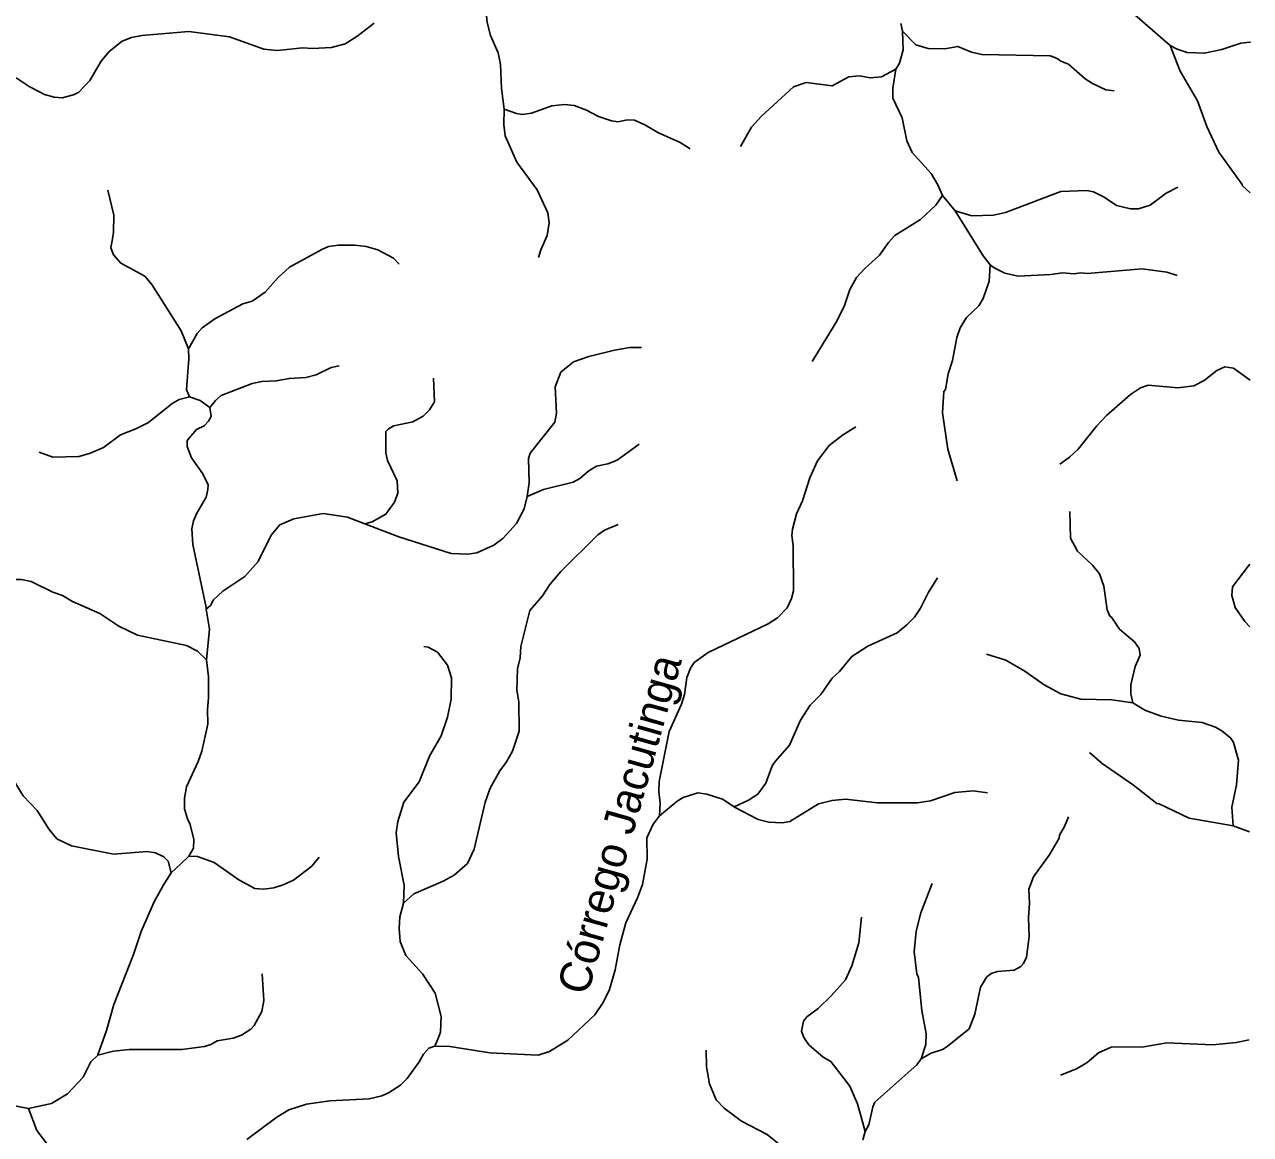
# Model space of a CAD drawing. Extents: x 500 to 555.2, y 9115.7 to 9171.
# Drawn here: x 549 to 555.13, y 9138.81 to 9144.36 of the extents above; entities that cross this region are included whole.
import ezdxf
from ezdxf.enums import TextEntityAlignment as Align

# ---------------------------------------------------------------- set-up
doc = ezdxf.new("R2010")
doc.units = 0
doc.header["$LTSCALE"] = 0.064
doc.layers.add('61', color=7, linetype='Continuous')
doc.layers.add('7', color=7, linetype='Continuous', lineweight=25)

msp = doc.modelspace()

# ---------------------------------------------------------------- linework, layer by layer
at = {"layer": '7'}
for p, q in [((553.6562, 9143.4292), (553.5928, 9143.5056)), ((555.0479, 9140.3515), (555.1299, 9140.3215))]:
    msp.add_line(p, q, dxfattribs=at)
for points in [[(551.3988, 9143.9379), (551.3851, 9144.0421), (551.3815, 9144.1623), (551.3685, 9144.2203), (551.3311, 9144.3079), (551.3147, 9144.3725), (551.3048, 9144.4766), (551.3209, 9144.649), (551.3179, 9144.7388), (551.3368, 9144.836)], [(554.7331, 9144.2576), (554.7328, 9144.2578), (554.5308, 9144.4333)], [(548.9572, 9144.0957), (549.0224, 9144.0519), (549.0979, 9144.0118), (549.1466, 9143.9984), (549.1866, 9143.9952), (549.2444, 9144.0096), (549.2707, 9144.0231), (549.3248, 9144.0821), (549.3823, 9144.1788), (549.422, 9144.2269), (549.4867, 9144.2785), (549.5345, 9144.2972), (549.5856, 9144.3067), (549.8212, 9144.328), (550.0246, 9144.3003), (550.1965, 9144.2395), (550.2634, 9144.233), (550.392, 9144.2459), (550.44, 9144.2428), (550.5343, 9144.2479), (550.6026, 9144.2658), (550.6621, 9144.3027), (550.7492, 9144.3699)], [(553.3588, 9144.1394), (553.3782, 9144.1697), (553.3959, 9144.2363), (553.3924, 9144.3284)], [(553.3924, 9144.3284), (553.3838, 9144.3669)], [(554.4516, 9144.0301), (554.4101, 9144.0349), (554.3431, 9144.0669), (554.3076, 9144.0907), (554.2232, 9144.1636), (554.1853, 9144.1783), (554.1719, 9144.1884), (554.1562, 9144.1969), (554.1317, 9144.2049), (553.79, 9144.213), (553.7388, 9144.2232), (553.6693, 9144.2524), (553.6043, 9144.2412), (553.5208, 9144.2431), (553.4602, 9144.261), (553.3924, 9144.3284)], [(555.1346, 9144.2746), (555.1308, 9144.2741), (555.0857, 9144.2682), (554.9914, 9144.2377), (554.9028, 9144.2182), (554.8175, 9144.2228), (554.7683, 9144.2388), (554.7331, 9144.2576)], [(555.1337, 9143.5192), (555.094, 9143.5541), (555.0932, 9143.5622), (554.9765, 9143.7226), (554.9168, 9143.8518), (554.869, 9143.9803), (554.7831, 9144.1294), (554.7331, 9144.2576)], [(552.5821, 9143.7511), (552.6366, 9143.8491), (552.6862, 9143.902), (552.8466, 9144.0507), (552.9115, 9144.0722), (553.0401, 9144.0559), (553.124, 9144.1006), (553.1781, 9144.105), (553.2303, 9144.0952), (553.288, 9144.1006), (553.3588, 9144.1394)], [(553.5928, 9143.5056), (553.5698, 9143.5605), (553.537, 9143.6162), (553.4406, 9143.7224), (553.4139, 9143.7809), (553.3912, 9143.8944), (553.3452, 9143.9932), (553.3452, 9144.0434), (553.3588, 9144.1394)], [(552.33, 9143.7402), (552.2793, 9143.7718), (552.1679, 9143.821), (552.1034, 9143.8606), (552.0513, 9143.8828), (552.0171, 9143.8852), (551.9679, 9143.8755), (551.9365, 9143.8799), (551.871, 9143.9012), (551.8115, 9143.9328), (551.7496, 9143.9576), (551.7011, 9143.9623), (551.6381, 9143.9555), (551.5353, 9143.9179), (551.4904, 9143.9116), (551.4605, 9143.9164), (551.3988, 9143.9379)], [(551.571, 9143.1957), (551.5826, 9143.2347), (551.615, 9143.3065), (551.6244, 9143.3689), (551.6179, 9143.4194), (551.565, 9143.5347), (551.4631, 9143.6732), (551.4047, 9143.8056), (551.3982, 9143.8615), (551.3988, 9143.9379)], [(549.4154, 9143.5324), (549.4461, 9143.4074), (549.4443, 9143.3233), (549.4387, 9143.2894), (549.43, 9143.2442), (549.4446, 9143.2092), (549.4807, 9143.1679), (549.6005, 9143.1022), (549.6356, 9143.0612), (549.782, 9142.8295), (549.8196, 9142.7384)], [(554.7707, 9143.5473), (554.7133, 9143.5177), (554.6327, 9143.4572), (554.5748, 9143.4391), (554.5347, 9143.4392), (554.4633, 9143.4557), (554.4021, 9143.4975), (554.3484, 9143.5244), (554.3157, 9143.5309), (554.1854, 9143.526), (553.9089, 9143.4209), (553.8491, 9143.4083), (553.7396, 9143.4038), (553.6562, 9143.4292)], [(552.9406, 9142.6752), (553.0646, 9142.8765), (553.1024, 9142.9552), (553.1289, 9143.036), (553.1619, 9143.0962), (553.2037, 9143.1417), (553.2776, 9143.2075), (553.3223, 9143.2717), (553.3546, 9143.3056), (553.4834, 9143.387), (553.56, 9143.4572), (553.5928, 9143.5056)], [(553.8322, 9143.159), (553.7967, 9143.2042), (553.6562, 9143.4292)], [(550.8738, 9143.1621), (550.8452, 9143.1928), (550.7672, 9143.2338), (550.7082, 9143.2519), (550.6518, 9143.2586), (550.5693, 9143.2586), (550.5207, 9143.2504), (550.4866, 9143.2369), (550.3241, 9143.1471), (550.2676, 9143.0959), (550.2031, 9143.0232), (550.1375, 9142.977), (550.0914, 9142.9634), (549.9512, 9142.8887), (549.8871, 9142.8446), (549.8625, 9142.815), (549.8196, 9142.7384)], [(553.6667, 9142.0777), (553.6195, 9142.2371), (553.5929, 9142.4183), (553.6004, 9142.5245), (553.6076, 9142.5359), (553.6218, 9142.6135), (553.6437, 9142.6812), (553.6651, 9142.796), (553.6808, 9142.8434), (553.7129, 9142.8949), (553.7745, 9142.9533), (553.7969, 9142.9911), (553.827, 9143.077), (553.8322, 9143.159)], [(554.7683, 9143.1063), (554.7159, 9143.1225), (554.5932, 9143.1389), (554.3179, 9143.1167), (554.2835, 9143.1191), (554.2524, 9143.1143), (554.1942, 9143.1192), (554.1351, 9143.111), (553.9717, 9143.1029), (553.9054, 9143.1175), (553.8513, 9143.144), (553.8322, 9143.159)], [(549.8196, 9142.7384), (549.8212, 9142.6888), (549.8096, 9142.5345), (549.8237, 9142.4982)], [(552.0874, 9142.7447), (552.0275, 9142.7449), (551.951, 9142.7321), (551.8231, 9142.7009), (551.746, 9142.6743), (551.6824, 9142.6224), (551.6538, 9142.5479), (551.6607, 9142.4164), (551.6522, 9142.3717), (551.5296, 9142.2171), (551.5215, 9142.1895), (551.5244, 9142.0672), (551.5139, 9141.9995)], [(550.5742, 9142.653), (550.5337, 9142.6449), (550.4579, 9142.6085), (550.4058, 9142.596), (550.3243, 9142.591), (550.2581, 9142.578), (550.1866, 9142.5746), (550.1385, 9142.5645), (549.9822, 9142.5047), (549.9537, 9142.4802), (549.9256, 9142.4453)], [(551.0451, 9142.5921), (551.0509, 9142.4735), (551.0259, 9142.4335), (550.9935, 9142.4012), (550.9426, 9142.3727), (550.8474, 9142.3527), (550.82, 9142.3385), (550.8077, 9142.3245), (550.8063, 9142.2188), (550.8153, 9142.1797), (550.8633, 9142.0776), (550.8662, 9142.0164), (550.8507, 9141.9714), (550.8067, 9141.9111), (550.7391, 9141.873), (550.7011, 9141.863)], [(555.1326, 9142.5815), (555.1207, 9142.5902), (555.0488, 9142.6428), (555.0063, 9142.6484), (554.9654, 9142.63), (554.9024, 9142.5799), (554.8516, 9142.5537), (554.7708, 9142.5435), (554.6226, 9142.5565), (554.5839, 9142.5428), (554.5334, 9142.5095), (554.4135, 9142.4045), (554.365, 9142.3526), (554.2724, 9142.2372), (554.2282, 9142.1963), (554.1801, 9142.1613)], [(549.0726, 9142.2221), (549.1396, 9142.1959), (549.2698, 9142.1995), (549.3238, 9142.214), (549.3932, 9142.2456), (549.4791, 9142.3089), (549.5565, 9142.338), (549.6199, 9142.3696), (549.7377, 9142.4644), (549.7726, 9142.4859), (549.8237, 9142.4982)], [(549.8237, 9142.4982), (549.8775, 9142.4808), (549.9256, 9142.4453)], [(549.9256, 9142.4453), (549.9331, 9142.4005), (549.92, 9142.3762), (549.8976, 9142.3535), (549.8594, 9142.3353), (549.812, 9142.2795), (549.8126, 9142.2493), (549.8343, 9142.1939), (549.891, 9142.1131), (549.9169, 9142.0582), (549.9168, 9142.035), (549.907, 9141.9957), (549.8605, 9141.9154), (549.8448, 9141.8775), (549.8367, 9141.8374), (549.8417, 9141.7588), (549.907, 9141.4434), (549.9081, 9141.4362)], [(553.1591, 9142.3481), (553.0927, 9142.3072), (553.0261, 9142.2555), (552.9673, 9142.1779), (552.9284, 9142.0935), (552.892, 9141.978), (552.8631, 9141.9136), (552.8417, 9141.836), (552.8384, 9141.8047), (552.8465, 9141.7528), (552.8481, 9141.5271), (552.8379, 9141.4892), (552.8165, 9141.4424), (552.7681, 9141.3923), (552.7206, 9141.3627), (552.4209, 9141.2186), (552.3508, 9141.1683), (552.3325, 9141.1399), (552.3142, 9141.0932), (552.3018, 9141.0081), (552.2876, 9140.9601), (552.2251, 9140.8233), (552.1754, 9140.573), (552.1741, 9140.5226), (552.1804, 9140.4649), (552.1765, 9140.4001)], [(552.0747, 9142.2615), (551.9656, 9142.181), (551.9177, 9142.1628), (551.8618, 9142.151), (551.8236, 9142.1287), (551.7786, 9142.0892), (551.7448, 9142.0714), (551.5967, 9142.0348), (551.5139, 9141.9995)], [(551.5139, 9141.9995), (551.5001, 9141.9386), (551.4617, 9141.864), (551.3927, 9141.7901), (551.3467, 9141.7558), (551.2627, 9141.7173), (551.2168, 9141.7103), (551.1334, 9141.7141), (550.8727, 9141.7979), (550.7011, 9141.863)], [(554.2303, 9141.9246), (554.2344, 9141.7905), (554.268, 9141.7256), (554.3446, 9141.6556), (554.3781, 9141.6124), (554.4002, 9141.5515), (554.4177, 9141.4327), (554.4307, 9141.4011), (554.4392, 9141.3962), (554.4791, 9141.3358), (554.5534, 9141.2713), (554.577, 9141.2393), (554.5817, 9141.2051), (554.5572, 9141.1486), (554.5361, 9141.0567), (554.5361, 9141.0114), (554.5458, 9140.9663)], [(550.7011, 9141.863), (550.6157, 9141.8954), (550.4937, 9141.9151), (550.3461, 9141.8871), (550.2763, 9141.8577), (550.2336, 9141.8053), (550.1679, 9141.6742), (550.1012, 9141.5997), (549.9919, 9141.526), (549.9451, 9141.4818), (549.9301, 9141.454), (549.9081, 9141.4362)], [(551.9705, 9141.8597), (551.9018, 9141.8315), (551.868, 9141.8078), (551.6834, 9141.6249), (551.6282, 9141.5596), (551.5912, 9141.5024), (551.5271, 9141.4282), (551.4821, 9141.2489), (551.4785, 9141.1925), (551.4655, 9141.1365), (551.4622, 9141.0298), (551.4719, 9140.9714), (551.4751, 9140.8245), (551.4402, 9140.7249), (551.4113, 9140.6719), (551.3769, 9140.6266), (551.3287, 9140.5386), (551.3043, 9140.4688), (551.2488, 9140.2345), (551.2154, 9140.1619), (551.1487, 9140.1036), (551.0947, 9140.0732), (550.9469, 9140.01), (550.8951, 9139.9642)], [(555.1312, 9141.3476), (555.1304, 9141.3484), (555.1067, 9141.3737), (555.0582, 9141.4438), (555.0413, 9141.5042), (555.045, 9141.5466), (555.1249, 9141.6528), (555.1316, 9141.6616)], [(548.7933, 9141.3636), (548.8368, 9141.423), (548.8724, 9141.5271), (548.9023, 9141.5694), (548.9324, 9141.5836), (548.9842, 9141.5836), (549.0312, 9141.5738), (549.1401, 9141.5213), (549.1892, 9141.5032), (549.238, 9141.474), (549.3757, 9141.4132), (549.4713, 9141.35), (549.5639, 9141.3059), (549.8091, 9141.2538), (549.864, 9141.225), (549.9093, 9141.1821)], [(553.5682, 9141.5923), (553.5213, 9141.5177), (553.4832, 9141.4401), (553.4526, 9141.3961), (553.4151, 9141.3569), (553.3666, 9141.3174), (553.2189, 9141.2509), (553.1385, 9141.1984), (553.077, 9141.124), (553.0413, 9141.0894), (552.9837, 9141.0078), (552.9307, 9140.9545), (552.8827, 9140.8802), (552.8268, 9140.7547), (552.7548, 9140.6735), (552.741, 9140.6505), (552.7083, 9140.5643), (552.6681, 9140.5101), (552.6215, 9140.4799), (552.5496, 9140.446)], [(549.9081, 9141.4362), (549.9236, 9141.3351), (549.9093, 9141.1821)], [(550.9966, 9141.2494), (551.0188, 9141.2449), (551.0652, 9141.2195), (551.1148, 9141.1549), (551.1356, 9141.0913), (551.134, 9140.9852), (551.1148, 9140.8951), (551.0847, 9140.8016), (551.025, 9140.6996), (550.9738, 9140.5715), (550.8976, 9140.4698), (550.8667, 9140.3728), (550.8585, 9140.3151), (550.8707, 9140.1969), (550.8994, 9140.0542), (550.8951, 9139.9642)], [(549.9093, 9141.1821), (549.9201, 9141.0974), (549.9202, 9140.9911), (549.9136, 9140.9333), (549.9168, 9140.8606), (549.8856, 9140.7254), (549.8671, 9140.6722), (549.8085, 9140.5462), (549.7988, 9140.4892), (549.7991, 9140.4367), (549.8135, 9140.3855), (549.8284, 9140.358), (549.846, 9140.2823), (549.8446, 9140.2388), (549.8211, 9140.1991)], [(553.8139, 9141.2108), (553.91, 9141.18), (554.0051, 9141.1259), (554.1025, 9141.0561), (554.1859, 9141.0112), (554.2854, 9140.9853), (554.4401, 9140.9819), (554.5458, 9140.9663)], [(554.5458, 9140.9663), (554.6063, 9140.9307), (554.6869, 9140.8999), (554.7741, 9140.8804), (554.8936, 9140.8687), (554.9592, 9140.8441), (554.992, 9140.826), (555.036, 9140.79), (555.0492, 9140.7686), (555.074, 9140.6801), (555.0642, 9140.5561), (555.0406, 9140.4438), (555.0479, 9140.3515)], [(548.9218, 9140.8426), (548.9181, 9140.7609), (548.9266, 9140.6297), (548.9425, 9140.5823), (548.9922, 9140.5014), (549.0611, 9140.427), (549.1211, 9140.3318), (549.161, 9140.285), (549.2336, 9140.2502), (549.4433, 9140.2095), (549.612, 9140.2223), (549.6545, 9140.2159), (549.6966, 9140.1965), (549.718, 9140.1735), (549.7331, 9140.1163)], [(554.3287, 9140.7178), (554.3918, 9140.6621), (554.5496, 9140.5551), (554.666, 9140.4628), (554.678, 9140.4615), (554.8276, 9140.39), (555.0479, 9140.3515)], [(552.5496, 9140.446), (552.492, 9140.4848), (552.4135, 9140.5094), (552.3681, 9140.516), (552.2955, 9140.493), (552.2659, 9140.475), (552.1765, 9140.4001)], [(553.8182, 9140.5167), (553.7463, 9140.5259), (553.6541, 9140.5178), (553.5328, 9140.4752), (553.4673, 9140.4653), (553.2685, 9140.4653), (553.1069, 9140.4848), (553.0402, 9140.4783), (552.9719, 9140.4604), (552.8283, 9140.3725), (552.7907, 9140.3652), (552.7234, 9140.3694), (552.6699, 9140.3832), (552.5513, 9140.4449), (552.5496, 9140.446)], [(552.1765, 9140.4001), (552.1443, 9140.3596), (552.1132, 9140.2916), (552.1148, 9140.1848), (552.0921, 9140.0575), (552.0671, 9139.9906), (552.0082, 9139.8659), (551.9785, 9139.7549), (551.9556, 9139.6297), (551.926, 9139.5313), (551.8948, 9139.4658), (551.8535, 9139.4052), (551.718, 9139.2777), (551.6255, 9139.2216), (551.5697, 9139.2029), (551.3276, 9139.2137), (551.1281, 9139.2466), (551.053, 9139.2481)], [(554.2232, 9140.3961), (554.2039, 9140.3472), (554.1787, 9140.3043), (554.1766, 9140.2899), (554.131, 9140.2083), (554.0486, 9140.0948), (554.026, 9140.0332), (554.029, 9139.9629), (554.0242, 9139.8913), (554.0275, 9139.797), (554.0131, 9139.6939), (553.9992, 9139.661), (553.986, 9139.6465), (553.9523, 9139.6283), (553.868, 9139.6216), (553.8372, 9139.6122), (553.8151, 9139.5948), (553.7833, 9139.5433), (553.7554, 9139.4078), (553.7258, 9139.3351), (553.6168, 9139.2455), (553.5928, 9139.2318), (553.5359, 9139.2122), (553.4861, 9139.1849)], [(549.8211, 9140.1991), (549.7804, 9140.1614), (549.7331, 9140.1163)], [(550.4732, 9140.1944), (550.4365, 9140.1482), (550.3453, 9140.0792), (550.2937, 9140.055), (550.247, 9140.0409), (550.194, 9140.0338), (550.1506, 9140.0371), (550.0706, 9140.0801), (549.9477, 9140.1675), (549.8651, 9140.1976), (549.8211, 9140.1991)], [(549.7331, 9140.1163), (549.6931, 9140.0525), (549.6461, 9139.9676), (549.5826, 9139.8212), (549.5448, 9139.7063), (549.4459, 9139.457), (549.4085, 9139.3258), (549.3659, 9139.2049), (549.3649, 9139.2035)], [(553.5408, 9140.0616), (553.4846, 9139.9152), (553.4616, 9139.8233), (553.4519, 9139.7195), (553.465, 9139.6093), (553.4727, 9139.5912), (553.4897, 9139.4264), (553.5108, 9139.3102), (553.509, 9139.2563), (553.4861, 9139.1849)], [(550.8951, 9139.9642), (550.8765, 9139.8953), (550.8733, 9139.8364), (550.8791, 9139.7719), (550.9065, 9139.7021), (550.9913, 9139.6106), (551.0533, 9139.5128), (551.0843, 9139.3967), (551.0813, 9139.3186), (551.0665, 9139.2826), (551.053, 9139.2481)], [(553.1871, 9139.8929), (553.1745, 9139.7648), (553.14, 9139.6501), (553.1068, 9139.5792), (553.0367, 9139.4991), (552.97, 9139.4371), (552.9138, 9139.3941), (552.8971, 9139.3732), (552.8875, 9139.3229), (552.8999, 9139.2908), (552.9249, 9139.255), (552.9959, 9139.1936), (553.0339, 9139.1704), (553.1295, 9139.0476), (553.1675, 9138.9592), (553.206, 9138.821)], [(550.1885, 9139.6103), (550.1959, 9139.477), (550.1859, 9139.4217), (550.1484, 9139.3511), (550.1309, 9139.3327), (550.0838, 9139.3037), (550.0429, 9139.2887), (549.9635, 9139.2744), (549.9306, 9139.2559), (549.8994, 9139.2463), (549.7851, 9139.2318), (549.5219, 9139.2316), (549.4446, 9139.2235), (549.3649, 9139.2035)], [(554.1836, 9139.1031), (554.2642, 9139.1337), (554.318, 9139.1658), (554.3732, 9139.2142), (554.4371, 9139.243), (554.601, 9139.2449), (554.7165, 9139.2645), (554.9454, 9139.2547), (555.0635, 9139.2661), (555.1282, 9139.2794), (555.1287, 9139.2795)], [(551.053, 9139.2481), (551.0228, 9139.2374), (550.9947, 9139.2071), (550.9741, 9139.1697), (550.9136, 9139.0852), (550.8798, 9139.053), (550.8203, 9139.0142), (550.7869, 9138.9996), (550.7234, 9138.984), (550.5272, 9138.9741), (550.4097, 9138.9578), (550.3212, 9138.9284), (550.262, 9138.8925), (550.1111, 9138.781)], [(552.4107, 9139.2279), (552.4119, 9139.1448), (552.4277, 9139.0598), (552.4603, 9138.9798), (552.5, 9138.9368), (552.5874, 9138.8725), (552.7158, 9138.8056), (552.7935, 9138.7422), (552.917, 9138.6592), (552.9499, 9138.6214), (552.9801, 9138.5626), (553.0037, 9138.4889)], [(549.3649, 9139.2035), (549.3302, 9139.1692), (549.292, 9139.0924), (549.2144, 9139.0087), (549.1335, 9138.9614), (549.0185, 9138.9355)], [(553.4861, 9139.1849), (553.464, 9139.1536), (553.255, 9138.9675), (553.245, 9138.944), (553.2244, 9138.8539), (553.206, 9138.821)], [(549.0185, 9138.9355), (549.0183, 9138.9355), (548.8206, 9138.9741), (548.7422, 9138.9743), (548.6736, 9138.9675), (548.5924, 9138.9376)], [(549.1079, 9138.7615), (549.0595, 9138.826), (549.0185, 9138.9355)], [(553.206, 9138.821), (553.1939, 9138.7783), (553.1938, 9138.7782)]]:
    msp.add_lwpolyline(points, dxfattribs=at)

# ---------------------------------------------------------------- texts
at = {"layer": '61'}
msp.add_text('Córrego Jacutinga', height=0.16, rotation=74.291, dxfattribs=at).set_placement((552.0527, 9140.3381), align=Align.CENTER)

doc.saveas('drawing.dxf')
